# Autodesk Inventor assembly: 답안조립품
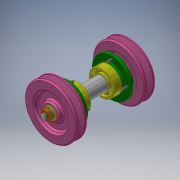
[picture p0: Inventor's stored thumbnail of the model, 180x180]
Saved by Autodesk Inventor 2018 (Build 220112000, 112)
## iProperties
Created: 2020-06
Part Number: 답안조립품
Material: 일반
Document SubType Name: Assembly
Designer: USER
Author: USER
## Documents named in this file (12)
- C:\Users\USER\Desktop\700606V1012\답안조립품.iam
- C:\Users\USER\Desktop\700606V1012\본체.ipt
- C:\Users\USER\Desktop\700606V1012\커버.ipt
- C:\Users\USER\Desktop\700606V1012\볼트 M4.ipt
- C:\Users\USER\Desktop\700606V1012\오일 실 20 32 5.ipt
- C:\Users\USER\Desktop\700606V1012\베어링 6204.ipt
- C:\Users\USER\Desktop\700606V1012\축.ipt
- C:\Users\USER\Desktop\700606V1012\Ű 5x5x12.ipt
- C:\Users\USER\Desktop\700606V1012\V-벨트풀리.ipt
- C:\Users\USER\Desktop\700606V1012\평면 와셔 10x21.ipt
- C:\Users\USER\Desktop\700606V1012\스프링 와셔 10.ipt
- C:\Users\USER\Desktop\700606V1012\너트 M10.ipt
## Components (4 placed, 2 different names)
1. Ű 5x5x12:1
2. Ű 5x5x12:2
3. V-벨트풀리:1
4. V-벨트풀리:2
